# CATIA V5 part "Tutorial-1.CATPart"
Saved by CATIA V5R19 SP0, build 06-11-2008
Part number: Part1
Bounding box of the stored display mesh (mm): x -24 to 119, y 0 to 47, z -43 to 1
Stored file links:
  D:\Shriniwas\v5_r19\Part files\C15\TUT1.CATPart
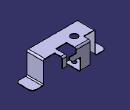
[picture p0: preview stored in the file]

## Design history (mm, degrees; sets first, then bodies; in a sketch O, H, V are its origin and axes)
SheetMetalParameters1: BendRadius 2, ReliefAxialLength 2, ReliefRadialLength 1, MinimumBendRadius 0, Thickness 1, KFactor 0.400515 {= log(min(100,max(20*SheetMetalParameters1.BendRadius,SheetMetalParameters1.Thickness)/SheetMetalParameters1.Thickness))/log(100)/2}
Body1 (main body)
  Sketch1 on xy-plane, origin (0, 0, 0), H (1, 0, 0), V (0, 1, 0)
    line L1 (0, 0) -> (95, 0)
    line L2 (95, 0) -> (95, 32)
    line L3 (95, 32) -> (76, 32)
    line L4 (76, 32) -> (76, 44)
    line L5 (76, 44) -> (68, 44)
    line L6 (68, 44) -> (68, 26)
    line L7 (68, 26) -> (47, 26)
    line L8 (47, 26) -> (47, 44)
    point P8 (47, 44)
    line L9 (47, 44) -> (20, 44)
    line L10 (20, 44) -> (20, 32)
    point P10 (20, 32)
    line L11 (20, 32) -> (0, 32)
    point P11 (0, 32)
    line L12 (0, 32) -> (0, 0)
    length L1 = 95
    length L2 = 32
    length L3 = 19
    length L5 = 8
    distance L1 L5 = 44
    distance L7 L1 = 26
    length L11 = 20
    length L9 = 27
    horizontal: L1 H, L3 H, L5 H, L7 H, L9 H, L11 H
    vertical: L2 V, L4 V, L6 V, L8 V, L10 V, L12 V
    coincidence: P8 L5, P10 L3, P11 V
  Wall1: Thickness 1, Profile Sketch1
  Flange1: Length 41, Radius 2, Angle 90, KFacteur 0.400515 {= log(min(100,max(20*Flange1.Radius,SheetMetalParameters1.Thickness)/SheetMetalParameters1.Thickness))/log(100)/2}, Guide edge [face of Wall1 | face of Wall1]
  Flange2: Length 41, Radius 2, Angle 90, KFacteur 0.400515 {= log(min(100,max(20*Flange2.Radius,SheetMetalParameters1.Thickness)/SheetMetalParameters1.Thickness))/log(100)/2}, Guide edge [face of Wall1 | face of Wall1]
  Flange3: Length 22, Radius 2, Angle 90, KFacteur 0.400515 {= log(min(100,max(20*Flange3.Radius,SheetMetalParameters1.Thickness)/SheetMetalParameters1.Thickness))/log(100)/2}, Guide edge [face of Flange2 | face of Flange2]
  Flange4: Length 22, Radius 2, Angle 90, KFacteur 0.400515 {= log(min(100,max(20*Flange4.Radius,SheetMetalParameters1.Thickness)/SheetMetalParameters1.Thickness))/log(100)/2}, Guide edge [face of Flange1 | face of Flange1]
  Sketch2 on face of Wall1, origin (47, 44, 0), H (-1, 0, 0), V (0, 0, 1)
    point P1 (0, 1)
    line L1 (0, 1) -> (0, -8)
    line L2 (0, -8) -> (-13, -8)
    line L3 (-13, -8) -> (-13, -18)
    line L4 (-13, -18) -> (8, -18)
    line L5 (8, -18) -> (8, -40)
    line L6 (8, -40) -> (27, -40)
    line L7 (27, -40) -> (27, 1)
    line L8 (27, 1) -> (0, 1)
    reference projected line E1 (27, 0) -> (27, 1) from edge [face of Wall1 | face of Wall1]
    reference projected line E2 (0, 1) -> (27, 1) from edge [face of Wall1 | face of Wall1]
    length L6 = 19
    length L7 = 41
    length L3 = 10
    distance L4 L8 = 19
    distance L3 L7 = 40
    coincidence: P1 V, L7 E1, L8 E2
    horizontal: L2 H, L4 H, L6 H
    vertical: L3 V, L5 V, L7 V, L1 V
  d_NewWallOnEdge1: NewWallOnEdge_HeightLimitOffset 0, NewWallOnEdge_WallProfile Sketch2, NewWallOnEdge_Length 27, NewWallOnEdge_Edge edge [face of Wall1 | face of Wall1], NewWallOnEdge_WidthOffset1 0, NewWallOnEdge_WidthOffset2 0, NewWallOnEdge_Angle 0, KFacteur 0.400515 {= log(min(100,max(20*d_NewWallOnEdge1.Radius,SheetMetalParameters1.Thickness)/SheetMetalParameters1.Thickness))/log(100)/2}, NewWallOnEdge_BendTable SheetMetalParameters1, NewWallOnEdge_BendRadiusValue 2 {= SheetMetalParameters1.BendRadius}
  Flange5: Length 19, Radius 2, Angle 90, KFacteur 0.400515 {= log(min(100,max(20*Flange5.Radius,SheetMetalParameters1.Thickness)/SheetMetalParameters1.Thickness))/log(100)/2}, Guide edge [face of Wall1 | face of Wall1]
  Flange6: Length 30, Radius 2, Angle 90, KFacteur 0.400515 {= log(min(100,max(20*Flange6.Radius,SheetMetalParameters1.Thickness)/SheetMetalParameters1.Thickness))/log(100)/2}, Guide edge [face of d_NewWallOnEdge1 | face of d_NewWallOnEdge1]
  Sketch3 on face of Wall1, origin (29.3791, 35.4737, 1), H (1, 0, 0), V (0, 1, 0)
    point P1 (-0.3791, -12.4737)
    reference projected line E1 (30.6209, 9.5263) -> (17.6209, 9.5263) from edge [face of d_NewWallOnEdge1 | face of d_NewWallOnEdge1]
    reference projected line E2 (-9.3791, 8.5263) -> (-9.3791, -3.4737) from edge [face of Wall1 | face of Wall1]
    distance P1 E1 = 22
    distance E2 P1 = 9
  Hole1: placed by Sketch3, at (29, 23, 1) direction (0, 0, -1), diameter 13, through (limit type 6)
  Sketch4 on face of Flange6, origin (31.6177, 25.4906, -42), H (1, 0, 0), V (0, 1, 0)
    point P1 (-2.6177, -2.4906)
    reference projected circle E1 centre (-2.6177, -2.4906) radius 6.5 from edge [face of Wall1 | face of Hole1]
    concentricity: P1 E1
  Hole2: placed by Sketch4, at (29, 23, -42) direction (0, 0, -1), diameter 8, through (limit type 6)
  Corner1: CornerChamferEdges (edge [face of Flange3 | face of Flange3]; edge [face of Flange3 | face of Flange3]; edge [face of Flange4 | face of Flange4]; edge [face of Flange4 | face of Flange4]), CornerRadius 7
  Corner2: CornerChamferEdges (edge [face of Wall1 | face of Wall1]; edge [face of Wall1 | face of Wall1]; edge [face of d_NewWallOnEdge1 | face of d_NewWallOnEdge1]; edge [face of Wall1 | face of Wall1]; edge [face of d_NewWallOnEdge1 | face of d_NewWallOnEdge1]; edge [face of Wall1 | face of Wall1]), CornerRadius 2
  Chamfer1: CornerChamferEdges edge [face of d_NewWallOnEdge1 | face of d_NewWallOnEdge1], ChamferType 1, ChamferLength1 6, ChamferLength2 0.5, ChamferAngle 45, ChamferPropagation 1, ChamferReverse false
